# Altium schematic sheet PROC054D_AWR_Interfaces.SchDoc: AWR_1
size 558 x 431 mm; Date: Not shown in title block; ApprovedBy: Not shown in title block; CheckedBy: Not shown in title block; Author: Not shown in title block; CompanyName: Not shown in title block; DrawnBy: a0271760; Engineer: Not shown in title block; Organization: Not shown in title block; Address1: Not shown in title block; Address2: Not shown in title block; Address3: Not shown in title block; Address4: Not shown in title block; DocumentNumber: 10; Revision: Use project pAWRameter SCH_Rev; SheetNumber: 10; SheetTotal: 19; PageSetup: Record=PageOptions¦CenterHorizontal=True¦CenterVertical=True¦PrintScale=1.00¦XCorrection=1.00¦YCorrection=1.00¦PrintKind=0¦BorderSize=5000000¦LeftOffset=0¦BottomOffset=0¦Orientation=2¦PaperLength=1000¦PaperWidth=1000¦Scale=100¦PaperSource=15¦PrintQuality=600¦MediaType=1¦DitherType=10¦PaperKind=Letter¦PrintScaleMode=1
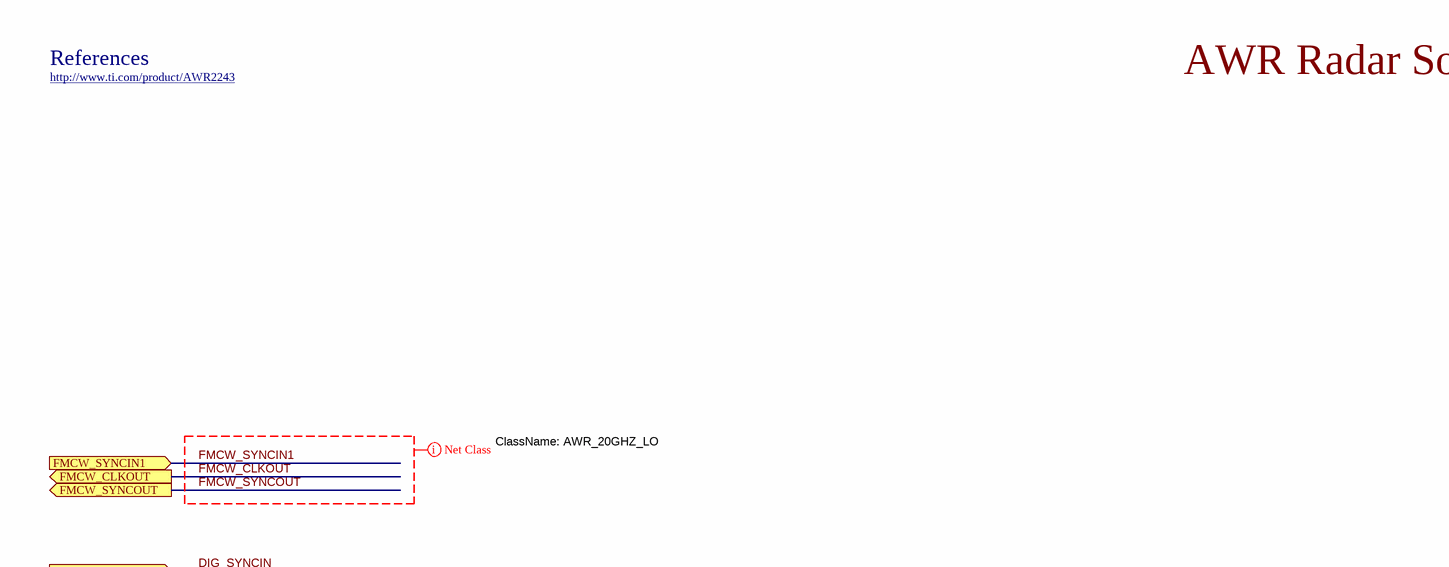
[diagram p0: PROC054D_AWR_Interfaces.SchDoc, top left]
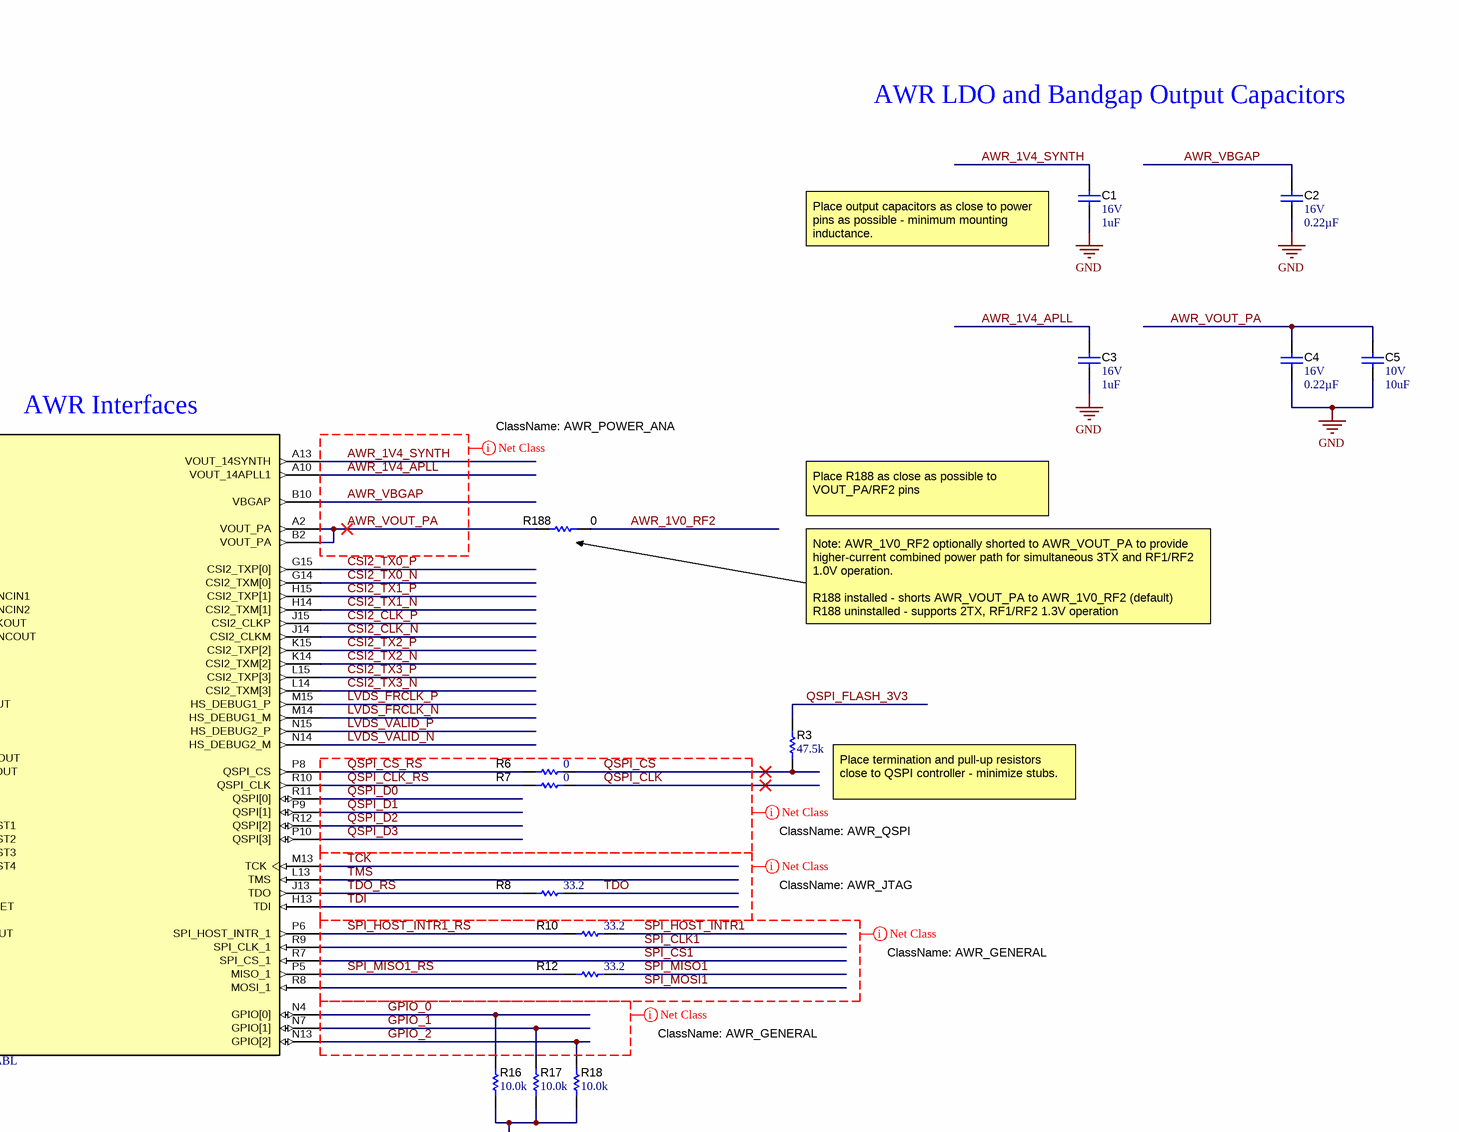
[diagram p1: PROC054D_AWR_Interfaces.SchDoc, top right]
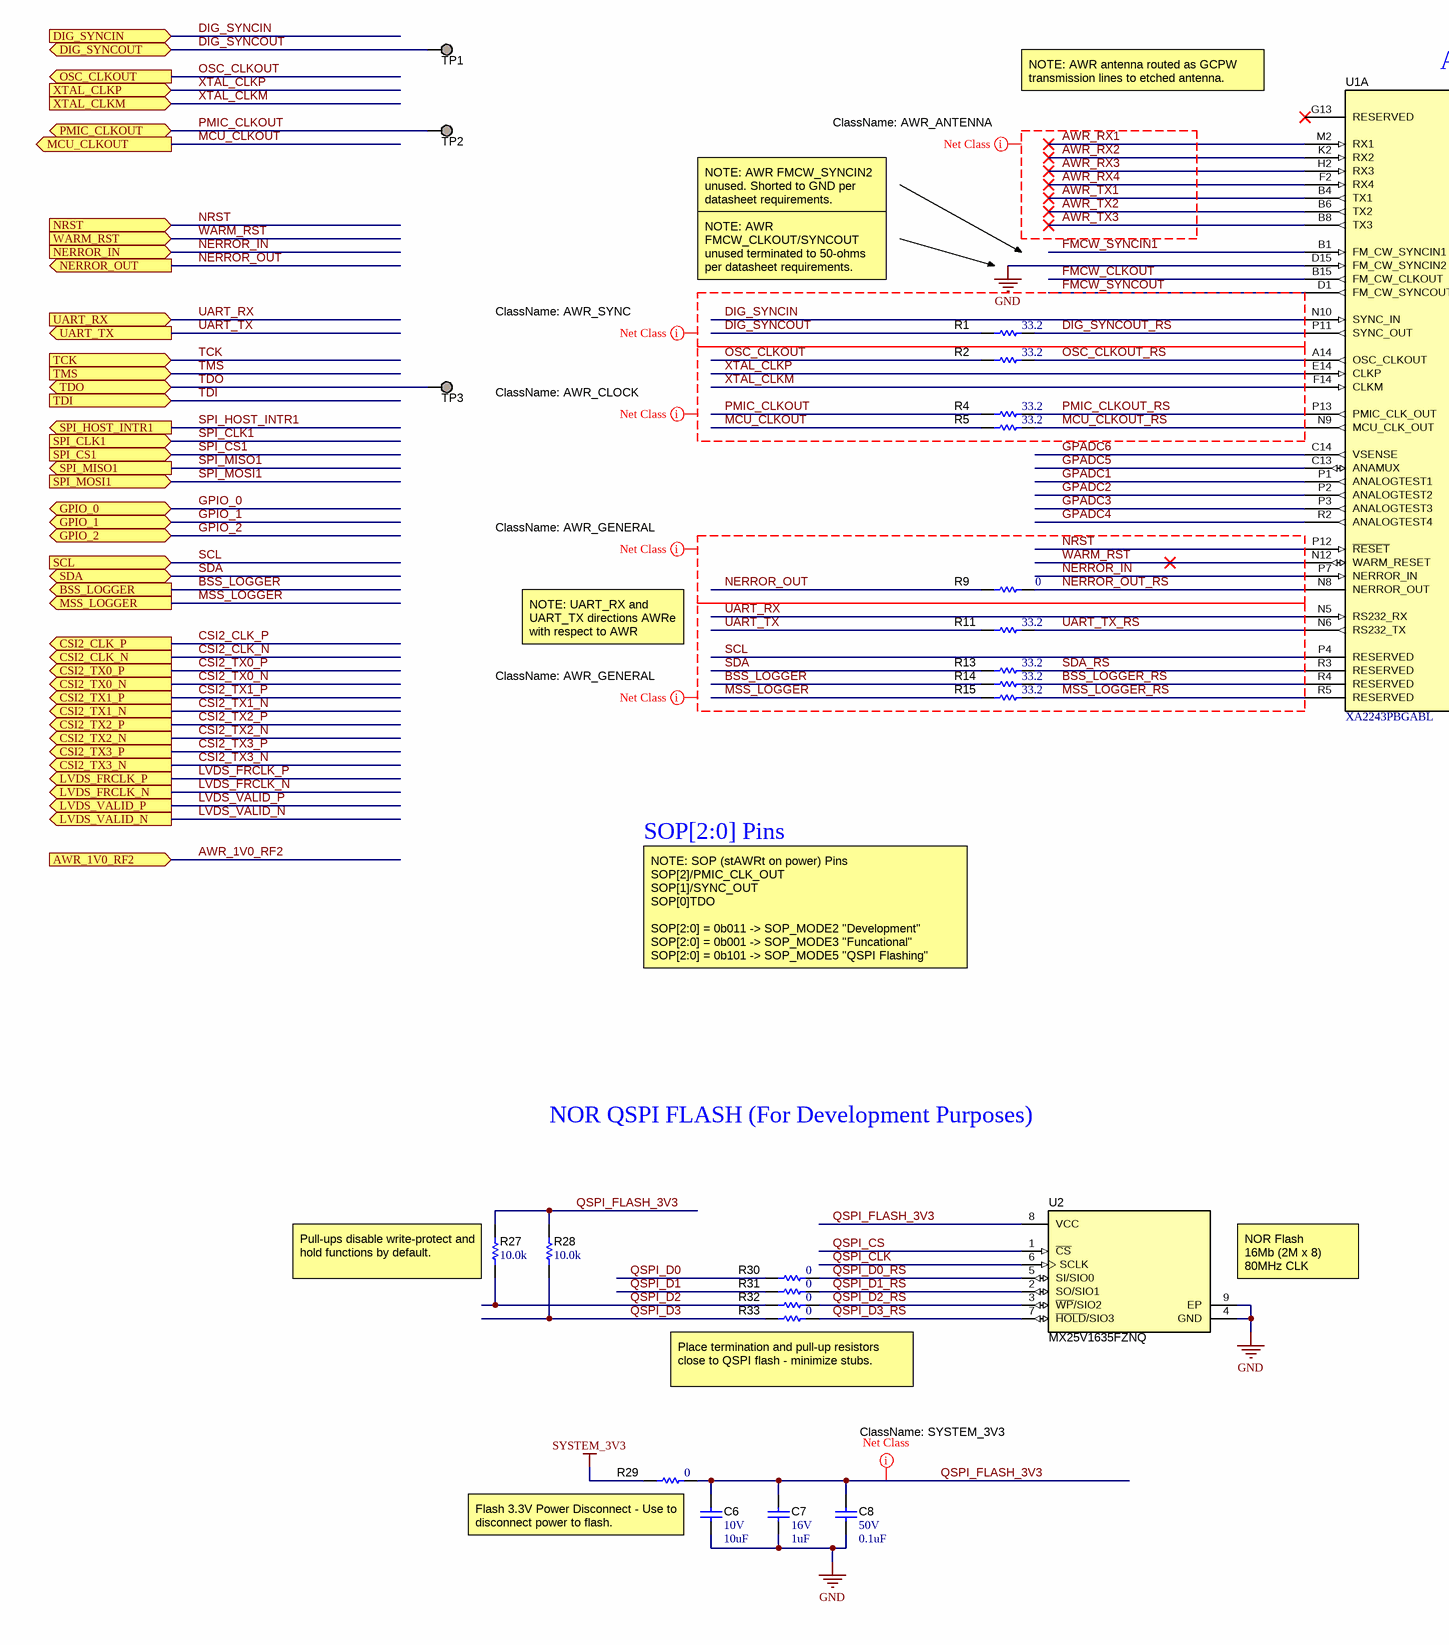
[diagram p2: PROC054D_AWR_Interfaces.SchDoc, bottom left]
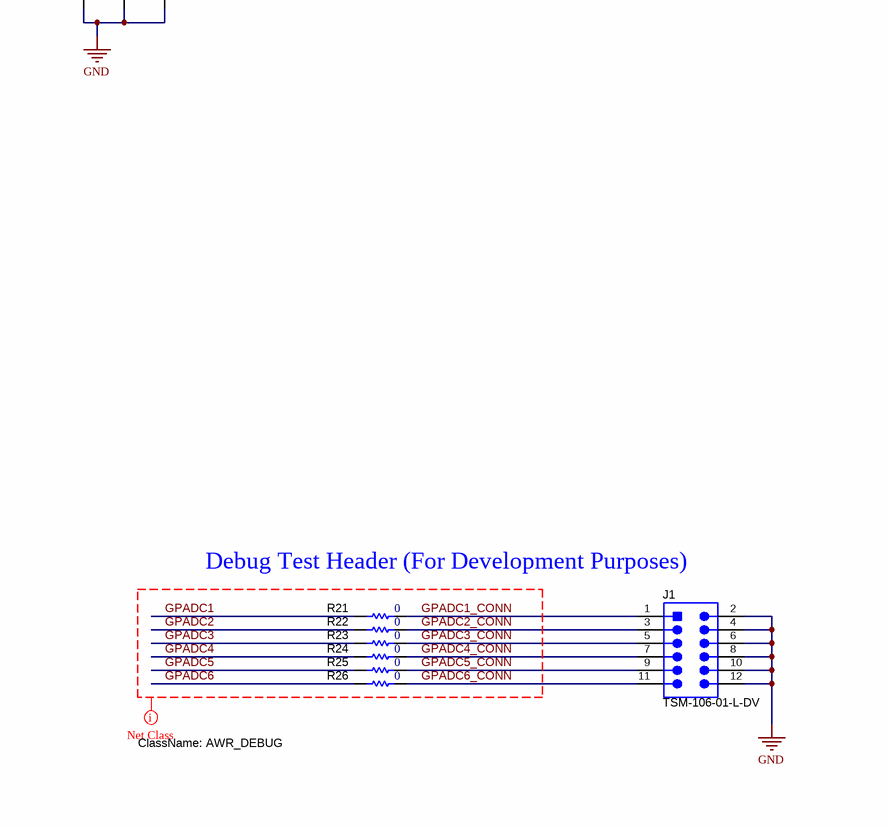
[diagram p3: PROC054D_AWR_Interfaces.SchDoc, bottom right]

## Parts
C1  VDC_V: 16V  ValueDisplayed: 1uF  [0603S]  (hidden comment: GCM188R71C105KA64D)
C2  VDC_V: 16V  ValueDisplayed: 0.22µF  [0402S]  (hidden comment: GCM155R71C224KE02D)
C3  VDC_V: 16V  ValueDisplayed: 1uF  [0603S]  (hidden comment: GCM188R71C105KA64D)
C4  VDC_V: 16V  ValueDisplayed: 0.22µF  [0402]  (hidden comment: GCM155R71C224KE02D)
C5  VDC_V: 10V  ValueDisplayed: 10uF  [0805]  (hidden comment: GCM21BR71A106KE22L)
C6  VDC_V: 10V  ValueDisplayed: 10uF  [0805L]  (hidden comment: GCM21BR71A106KE22L)
C7  VDC_V: 16V  ValueDisplayed: 1uF  [0603S]  (hidden comment: GCM188R71C105KA64D)
C8  VDC_V: 50V  ValueDisplayed: 0.1uF  [0402S]  (hidden comment: CGA2B3X7R1H104K050BB)
J1  TSM-106-01-L-DV  [Samtec_TSM-106-01-x-DV]
R1  ValueDisplayed: 33.2  [0402S]  (hidden comment: CRCW040233R2FKED)
R2  ValueDisplayed: 33.2  [0402S]  (hidden comment: CRCW040233R2FKED)
R3  ValueDisplayed: 47.5k  [0402]  (hidden comment: CRCW040247K5FKED)
R4  ValueDisplayed: 33.2  [0402S]  (hidden comment: CRCW040233R2FKED)
R5  ValueDisplayed: 33.2  [0402S]  (hidden comment: CRCW040233R2FKED)
R6  ValueDisplayed: 0  [0201]  (hidden comment: CRCW02010000Z0ED)
R7  ValueDisplayed: 0  [0201]  (hidden comment: CRCW02010000Z0ED)
R8  ValueDisplayed: 33.2  [0402S]  (hidden comment: CRCW040233R2FKED)
R9  ValueDisplayed: 0  [0402S]  (hidden comment: ERJ-2GE0R00X)
R10  ValueDisplayed: 33.2  [0402S]  (hidden comment: CRCW040233R2FKED)
R11  ValueDisplayed: 33.2  [0402S]  (hidden comment: CRCW040233R2FKED)
R12  ValueDisplayed: 33.2  [0402S]  (hidden comment: CRCW040233R2FKED)
R13  ValueDisplayed: 33.2  [0402S]  (hidden comment: CRCW040233R2FKED)
R14  ValueDisplayed: 33.2  [0402S]  (hidden comment: CRCW040233R2FKED)
R15  ValueDisplayed: 33.2  [0402S]  (hidden comment: CRCW040233R2FKED)
R16  ValueDisplayed: 10.0k  [0402]  (hidden comment: CRCW040210K0FKED)
R17  ValueDisplayed: 10.0k  [0402]  (hidden comment: CRCW040210K0FKED)
R18  ValueDisplayed: 10.0k  [0402]  (hidden comment: CRCW040210K0FKED)
R21  ValueDisplayed: 0  [0402]  (hidden comment: CRCW04020000Z0ED)
R22  ValueDisplayed: 0  [0402]  (hidden comment: CRCW04020000Z0ED)
R23  ValueDisplayed: 0  [0402]  (hidden comment: CRCW04020000Z0ED)
R24  ValueDisplayed: 0  [0402]  (hidden comment: CRCW04020000Z0ED)
R25  ValueDisplayed: 0  [0402]  (hidden comment: CRCW04020000Z0ED)
R26  ValueDisplayed: 0  [0402]  (hidden comment: CRCW04020000Z0ED)
R27  ValueDisplayed: 10.0k  [0402S]  (hidden comment: CRCW040210K0FKED)
R28  ValueDisplayed: 10.0k  [0402S]  (hidden comment: CRCW040210K0FKED)
R29  ValueDisplayed: 0  [0805_HV]  (hidden comment: CRCW08050000Z0EAHP)
R30  ValueDisplayed: 0  [0201]  (hidden comment: CRCW02010000Z0ED)
R31  ValueDisplayed: 0  [0201]  (hidden comment: CRCW02010000Z0ED)
R32  ValueDisplayed: 0  [0201]  (hidden comment: CRCW02010000Z0ED)
R33  ValueDisplayed: 0  [0201]  (hidden comment: CRCW02010000Z0ED)
R188  ValueDisplayed: 0  [0805L]  (hidden comment: PMR10EZPJ000)
TP1  TP_SM_1MM  [TP_SM_1MM]  (value not drawn)  (no BOM)
TP2  TP_SM_1MM  [TP_SM_1MM]  (value not drawn)  (no BOM)
TP3  TP_SM_1MM  [TP_SM_1MM]  (value not drawn)  (no BOM)
U1  XA2243PBGABL  [ABL0161A]  (part A of 2)
U2  MX25V1635FZNQ  [WSON-8L_6x5MM_EP]

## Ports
AWR_1V0_RF2 (in), BSS_LOGGER (out), CSI2_CLK_N (out), CSI2_CLK_P (out), CSI2_TX0_N (out), CSI2_TX0_P (out), CSI2_TX1_N (out), CSI2_TX1_P (out), CSI2_TX2_N (out), CSI2_TX2_P (out), CSI2_TX3_N (out), CSI2_TX3_P (out), DIG_SYNCIN (in), DIG_SYNCOUT (bidir), FMCW_CLKOUT (out), FMCW_SYNCIN1 (in), FMCW_SYNCOUT (out), GPIO_0 (bidir), GPIO_1 (bidir), GPIO_2 (bidir), LVDS_FRCLK_N (out), LVDS_FRCLK_P (out), LVDS_VALID_N (out), LVDS_VALID_P (out), MCU_CLKOUT (out), MSS_LOGGER (out), NERROR_IN (in), NERROR_OUT (out), NRST (in), OSC_CLKOUT (out), PMIC_CLKOUT (bidir), SCL (in), SDA (bidir), SPI_CLK1 (in), SPI_CS1 (in), SPI_HOST_INTR1 (out), SPI_MISO1 (out), SPI_MOSI1 (in), TCK (in), TDI (in), TDO (bidir), TMS (in), UART_RX (in), UART_TX (out), WARM_RST (in), XTAL_CLKM (in), XTAL_CLKP (in)

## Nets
GND: C1.2 C2.2 C3.2 C4.2 C5.2 C6.2 C7.2 C8.2 J1.2 J1.4 J1.6 J1.8 J1.10 J1.12 R16.1 R17.1 R18.1 U1.D15(FM_CW_SYNCIN2) U2.4(GND) U2.9(EP)
SYSTEM_3V3: R29.2
AWR_1V0_RF2: R188.2 ; port AWR_1V0_RF2
AWR_1V4_APLL: C3.1 U1.A10(VOUT_14APLL1)
AWR_1V4_SYNTH: C1.1 U1.A13(VOUT_14SYNTH)
AWR_RX1: U1.M2(RX1)
AWR_RX2: U1.K2(RX2)
AWR_RX3: U1.H2(RX3)
AWR_RX4: U1.F2(RX4)
AWR_TX1: U1.B4(TX1)
AWR_TX2: U1.B6(TX2)
AWR_TX3: U1.B8(TX3)
AWR_VBGAP: C2.1 U1.B10(VBGAP)
AWR_VOUT_PA: C4.1 C5.1 R188.1 U1.A2(VOUT_PA) U1.B2(VOUT_PA)
BSS_LOGGER: R14.1 ; port BSS_LOGGER
BSS_LOGGER_RS: R14.2 U1.R4(RESERVED)
CSI2_CLK_N: U1.J14(CSI2_CLKM) ; port CSI2_CLK_N
CSI2_CLK_P: U1.J15(CSI2_CLKP) ; port CSI2_CLK_P
CSI2_TX0_N: U1.G14(CSI2_TXM[0]) ; port CSI2_TX0_N
CSI2_TX0_P: U1.G15(CSI2_TXP[0]) ; port CSI2_TX0_P
CSI2_TX1_N: U1.H14(CSI2_TXM[1]) ; port CSI2_TX1_N
CSI2_TX1_P: U1.H15(CSI2_TXP[1]) ; port CSI2_TX1_P
CSI2_TX2_N: U1.K14(CSI2_TXM[2]) ; port CSI2_TX2_N
CSI2_TX2_P: U1.K15(CSI2_TXP[2]) ; port CSI2_TX2_P
CSI2_TX3_N: U1.L14(CSI2_TXM[3]) ; port CSI2_TX3_N
CSI2_TX3_P: U1.L15(CSI2_TXP[3]) ; port CSI2_TX3_P
DIG_SYNCIN: U1.N10(SYNC_IN) ; port DIG_SYNCIN
DIG_SYNCOUT: R1.1 TP1.1 ; port DIG_SYNCOUT
DIG_SYNCOUT_RS: R1.2 U1.P11(SYNC_OUT)
FMCW_CLKOUT: U1.B15(FM_CW_CLKOUT) ; port FMCW_CLKOUT
FMCW_SYNCIN1: U1.B1(FM_CW_SYNCIN1) ; port FMCW_SYNCIN1
FMCW_SYNCOUT: U1.D1(FM_CW_SYNCOUT) ; port FMCW_SYNCOUT
GPADC1: R21.1 U1.P1(ANALOGTEST1)
GPADC1_CONN: J1.1 R21.2
GPADC2: R22.1 U1.P2(ANALOGTEST2)
GPADC2_CONN: J1.3 R22.2
GPADC3: R23.1 U1.P3(ANALOGTEST3)
GPADC3_CONN: J1.5 R23.2
GPADC4: R24.1 U1.R2(ANALOGTEST4)
GPADC4_CONN: J1.7 R24.2
GPADC5: R25.1 U1.C13(ANAMUX)
GPADC5_CONN: J1.9 R25.2
GPADC6: R26.1 U1.C14(VSENSE)
GPADC6_CONN: J1.11 R26.2
GPIO_0: R16.2 U1.N4(GPIO[0]) ; port GPIO_0
GPIO_1: R17.2 U1.N7(GPIO[1]) ; port GPIO_1
GPIO_2: R18.2 U1.N13(GPIO[2]) ; port GPIO_2
LVDS_FRCLK_N: U1.M14(HS_DEBUG1_M) ; port LVDS_FRCLK_N
LVDS_FRCLK_P: U1.M15(HS_DEBUG1_P) ; port LVDS_FRCLK_P
LVDS_VALID_N: U1.N14(HS_DEBUG2_M) ; port LVDS_VALID_N
LVDS_VALID_P: U1.N15(HS_DEBUG2_P) ; port LVDS_VALID_P
MCU_CLKOUT: R5.1 ; port MCU_CLKOUT
MCU_CLKOUT_RS: R5.2 U1.N9(MCU_CLK_OUT)
MSS_LOGGER: R15.1 ; port MSS_LOGGER
MSS_LOGGER_RS: R15.2 U1.R5(RESERVED)
NERROR_IN: U1.P7(NERROR_IN) ; port NERROR_IN
NERROR_OUT: R9.1 ; port NERROR_OUT
NERROR_OUT_RS: R9.2 U1.N8(NERROR_OUT)
NRST: U1.P12(~{RESET}) ; port NRST
OSC_CLKOUT: R2.1 ; port OSC_CLKOUT
OSC_CLKOUT_RS: R2.2 U1.A14(OSC_CLKOUT)
PMIC_CLKOUT: R4.1 TP2.1 ; port PMIC_CLKOUT
PMIC_CLKOUT_RS: R4.2 U1.P13(PMIC_CLK_OUT)
QSPI_CLK: R7.2 U2.6(SCLK)
QSPI_CLK_RS: R7.1 U1.R10(QSPI_CLK)
QSPI_CS: R3.1 R6.2 U2.1(~{CS})
QSPI_CS_RS: R6.1 U1.P8(QSPI_CS)
QSPI_D0: R30.1 U1.R11(QSPI[0])
QSPI_D0_RS: R30.2 U2.5(SI/SIO0)
QSPI_D1: R31.1 U1.P9(QSPI[1])
QSPI_D1_RS: R31.2 U2.2(SO/SIO1)
QSPI_D2: R27.2 R32.1 U1.R12(QSPI[2])
QSPI_D2_RS: R32.2 U2.3(~{WP}/SIO2)
QSPI_D3: R28.2 R33.1 U1.P10(QSPI[3])
QSPI_D3_RS: R33.2 U2.7(~{HOLD}/SIO3)
QSPI_FLASH_3V3: C6.1 C7.1 C8.1 R3.2 R27.1 R28.1 R29.1 U2.8(VCC)
SCL: U1.P4(RESERVED) ; port SCL
SDA: R13.1 ; port SDA
SDA_RS: R13.2 U1.R3(RESERVED)
SPI_CLK1: U1.R9(SPI_CLK_1) ; port SPI_CLK1
SPI_CS1: U1.R7(SPI_CS_1) ; port SPI_CS1
SPI_HOST_INTR1: R10.2 ; port SPI_HOST_INTR1
SPI_HOST_INTR1_RS: R10.1 U1.P6(SPI_HOST_INTR_1)
SPI_MISO1: R12.2 ; port SPI_MISO1
SPI_MISO1_RS: R12.1 U1.P5(MISO_1)
SPI_MOSI1: U1.R8(MOSI_1) ; port SPI_MOSI1
TCK: U1.M13(TCK) ; port TCK
TDI: U1.H13(TDI) ; port TDI
TDO: R8.2 TP3.1 ; port TDO
TDO_RS: R8.1 U1.J13(TDO)
TMS: U1.L13(TMS) ; port TMS
UART_RX: U1.N5(RS232_RX) ; port UART_RX
UART_TX: R11.1 ; port UART_TX
UART_TX_RS: R11.2 U1.N6(RS232_TX)
WARM_RST: U1.N12(WARM_RESET) ; port WARM_RST
XTAL_CLKM: U1.F14(CLKM) ; port XTAL_CLKM
XTAL_CLKP: U1.E14(CLKP) ; port XTAL_CLKP

Not connected (* = marked no-connect by the designer): U1 G13(RESERVED)*

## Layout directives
net class AWR_DEBUG: GPADC1, GPADC1_CONN, GPADC2, GPADC2_CONN, GPADC3, GPADC3_CONN, GPADC4, GPADC4_CONN, GPADC5, GPADC5_CONN, GPADC6, GPADC6_CONN
net class AWR_QSPI: QSPI_CLK, QSPI_CLK_RS, QSPI_CS, QSPI_CS_RS, QSPI_D0, QSPI_D1, QSPI_D2, QSPI_D3
net class AWR_JTAG: TCK, TDI, TDO, TDO_RS, TMS
net class AWR_POWER_ANA: AWR_1V4_APLL, AWR_1V4_SYNTH, AWR_VBGAP, AWR_VOUT_PA
net class AWR_ANTENNA: AWR_RX1, AWR_RX2, AWR_RX3, AWR_RX4, AWR_TX1, AWR_TX2, AWR_TX3
net class SYSTEM_3V3: QSPI_FLASH_3V3
net class AWR_20GHZ_LO: FMCW_CLKOUT, FMCW_SYNCIN1, FMCW_SYNCOUT
net class AWR_GENERAL: BSS_LOGGER, BSS_LOGGER_RS, GPIO_0, GPIO_1, GPIO_2, MSS_LOGGER, MSS_LOGGER_RS, NERROR_IN, NERROR_OUT, NERROR_OUT_RS, NRST, SCL, SDA, SDA_RS, SPI_CLK1, SPI_CS1, SPI_HOST_INTR1, SPI_HOST_INTR1_RS, SPI_MISO1, SPI_MISO1_RS, SPI_MOSI1, UART_RX, UART_TX, UART_TX_RS, WARM_RST
net class AWR_CLOCK: MCU_CLKOUT, MCU_CLKOUT_RS, OSC_CLKOUT, OSC_CLKOUT_RS, PMIC_CLKOUT, PMIC_CLKOUT_RS, XTAL_CLKM, XTAL_CLKP
net class AWR_SYNC: DIG_SYNCIN, DIG_SYNCOUT, DIG_SYNCOUT_RS, FMCW_SYNCOUT

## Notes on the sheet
- References
- http://www.ti.com/product/AWR2243
- AWR Radar SoC - Interfaces
- AWR LDO and Bandgap Output Capacitors
- (near C1) Place output capacitors as close to power pins as possible - minimum mounting inductance.
- NOTE: AWR antenna routed as GCPW transmission lines to etched antenna.
- (near U1) AWR Interfaces
- NOTE: AWR FMCW_SYNCIN2 unused. Shorted to GND per datasheet requirements.
- Place R188 as close as possible to VOUT_PA/RF2 pins
- NOTE: AWR FMCW_CLKOUT/SYNCOUT unused terminated to 50-ohms per datasheet requirements.
- Note: AWR_1V0_RF2 optionally shorted to AWR_VOUT_PA to provide higher-current combined power path for simultaneous 3TX and RF1/RF2 1.0V operation.
  R188 installed - shorts AWR_VOUT_PA to AWR_1V0_RF2 (default)
  R188 uninstalled - supports 2TX, RF1/RF2 1.3V operation
- (near R3) Place termination and pull-up resistors close to QSPI controller - minimize stubs.
- NOTE: UART_RX and UART_TX directions AWRe with respect to AWR
- SOP[2:0] Pins
- NOTE: SOP (stAWRt on power) Pins SOP[2]/PMIC_CLK_OUT
  SOP[1]/SYNC_OUT
  SOP[0]TDO
  SOP[2:0] = 0b011 -> SOP_MODE2 "Development"
  SOP[2:0]	= 0b001 -> SOP_MODE3 "Funcational"
  SOP[2:0]	= 0b101 -> SOP_MODE5 "QSPI Flashing"
- NOR QSPI FLASH (For Development Purposes)
- (near R27) Pull-ups disable write-protect and hold functions by default.
- (near U2) NOR Flash
  16Mb (2M x 8)
  80MHz CLK
- Debug Test Header (For Development Purposes)
- (near R33) Place termination and pull-up resistors close to QSPI flash - minimize stubs.
- (near R29) Flash 3.3V Power Disconnect - Use to disconnect power to flash.

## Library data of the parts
C1 C7 = CMP-0007136-5: CAP, CERM, 1 uF, 16 V, +/- 10%, X7R, AEC-Q200 Grade 1, 0603; Manufacturer: MuRata; TaMin_C: -55°C; Polarized: N; SizeAreaWB_mm2: 4.68; Value1: Unknown; U/M: EA; Value: 1uF; TaMax_C: 125°C; SizeZ_mm: 1; SizeX_mm: 1.6; SizeY_mm: 0.8; Cap_Case: 0603; SizeArea_mm2: 1.28; CompType: Capacitor; AEC Qualified: Y; Cap_F: 1µF; AEC Category: Q200
C2 = CMP-0078265-1: CAP, CERM, 0.22 µF, 16 V,+/- 10%, X7R, AEC-Q200 Grade 1, 0402; Manufacturer: MuRata; TaMin_C: -55°C; Polarized: N; SizeAreaWB_mm2: 3; U/M: EA; Value: 0.22uF; TaMax_C: 125°C; SizeZ_mm: 0.6; SizeX_mm: 1; SizeY_mm: 0.5; Cap_Case: 0402; CompType: Capacitor; AEC Qualified: Y; Cap_F: 220nF; AEC Category: Q200
C3 = CMP-0007136-5: CAP, CERM, 1 uF, 16 V, +/- 10%, X7R, AEC-Q200 Grade 1, 0603; Manufacturer: MuRata; TaMin_C: -55°C; Polarized: N; SizeAreaWB_mm2: 4.68; Value1: Unknown; U/M: EA; Value: 1uF; TaMax_C: 125°C; SizeZ_mm: 1; SizeX_mm: 1.6; SizeY_mm: 0.8; Cap_Case: 0603; SizeArea_mm2: 1.28; AEC Qualified: Y; Cap_F: 1µF; AEC Category: Q200
C4 = CMP-0078265-1: CAP, CERM, 0.22 µF, 16 V,+/- 10%, X7R, AEC-Q200 Grade 1, 0402; Manufacturer: MuRata; TaMin_C: -55°C; Polarized: N; SizeAreaWB_mm2: 3; U/M: EA; Value: 0.22uF; TaMax_C: 125°C; SizeZ_mm: 0.6; SizeX_mm: 1; SizeY_mm: 0.5; CompType: Capacitor; AEC Qualified: Y; Cap_F: 220nF; AEC Category: Q200
C5 = CMP-0008017-2: CAP, CERM, 10 uF, 10 V, +/- 10%, X7R, 0805; Manufacturer: MuRata; TaMin_C: -55°C; Polarized: N; SizeAreaWB_mm2: 6.75; Value1: Unknown; U/M: EA; Value: 10uF; TaMax_C: 125°C; SizeZ_mm: 1.45; SizeX_mm: 2; SizeY_mm: 1.25; SizeArea_mm2: 2.5; Cap_F: 10µF; AEC Category: Q200
C6 = CMP-0008017-2: CAP, CERM, 10 uF, 10 V, +/- 10%, X7R, 0805; Manufacturer: MuRata; TaMin_C: -55°C; Polarized: N; SizeAreaWB_mm2: 6.75; Value1: Unknown; U/M: EA; Value: 10uF; TaMax_C: 125°C; SizeZ_mm: 1.45; SizeX_mm: 2; SizeY_mm: 1.25; Cap_Case: 0805; SizeArea_mm2: 2.5; CompType: Capacitor; Cap_F: 10µF; AEC Category: Q200
C8 = CMP-0006325-2: CAP, CERM, 0.1 uF, 50 V, +/- 10%, X7R, AEC-Q200 Grade 1, 0402; Manufacturer: TDK; TaMin_C: -55°C; ESR_ohm: 0.039064; Polarized: N; SizeAreaWB_mm2: 3; Value1: 0.039064 ohm; U/M: EA; Value: 0.1uF; TaMax_C: 125°C; SizeZ_mm: 0.6; SizeX_mm: 1; SizeY_mm: 0.5; Cap_Case: 0402; AEC Qualified: Y; Cap_F: 100nF; IRMS_A: 8.14669dA; AEC Category: Q200
J1 = CMP-0075594-2: Header, 2.54mm, 6x2, Gold, SMT; Manufacturer: Samtec; Pitch_mm: 2.54; Gender: Male; Cert_CSA: Y; Green_REACh: Passed; Current_A: 4.9A; Voltage_V: 475V; Shrouded: N; Green_Lifecycle: Active; Row_Count: 2
R1 R2 R4 R5 R8 R10-R13 = CMP-0026299-2: RES, 33.2, 1%, 0.063 W, AEC-Q200 Grade 0, 0402; Manufacturer: Vishay-Dale; Power_W: 63mW; TempCo: 100 ppm/C; Value_Code: 33R2; Value: 33.2; EIA_Code: E96; SizeX_mm: 1; SizeY_mm: 0.5; SizeZ_mm: 0.6; Value2: 0.063W; CompType: Resistor; AEC Qualified: Y; VDC_V: 50V; AEC Category: Q200; AEC Grade: 0
R3 = CMP-0026395-2: RES, 47.5 k, 1%, 0.063 W, AEC-Q200 Grade 0, 0402; Manufacturer: Vishay-Dale; Power_W: 63mW; TempCo: 100 ppm/C; Value_Code: 47k5; Value: 47.5k; EIA_Code: E96; SizeX_mm: 1; SizeY_mm: 0.5; SizeZ_mm: 0.6; Value2: 0.063W; AEC Qualified: Y; VDC_V: 50V; AEC Category: Q200; AEC Grade: 0
R6 R7 R30-R33 = CMP-0027008-4: RES, 0, 5%, 0.05 W, 0201; Manufacturer: Vishay-Dale; Power_W: 50mW; TempCo: ppm/C; Value_Code: 0000; Value: 0; EIA_Code: E24; SizeX_mm: 0.6; SizeY_mm: 0.3; SizeZ_mm: 0.26; Value2: 0.05W; SizeArea_mm2: 0.18; CompType: Resistor; AEC Qualified: N; AEC Category: Q200
R9 = CMP-0026992-3: RES, 0, 5%, 0.1 W, AEC-Q200 Grade 0, 0402; Manufacturer: Panasonic; Power_W: 100mW; TempCo: 600 ppm/C; Value_Code: 0000; Value: 0; EIA_Code: E24; SizeX_mm: 1; SizeY_mm: 0.5; SizeZ_mm: 0.6; Value2: 0.1W; CompType: Resistor; AEC Qualified: Y; VDC_V: 50V; AEC Category: Q200; SizeAreaWB_mm2: 3
R14 R15 = CMP-0026299-2: RES, 33.2, 1%, 0.063 W, AEC-Q200 Grade 0, 0402; Manufacturer: Vishay-Dale; Power_W: 63mW; TempCo: 100 ppm/C; Value_Code: 33R2; Value: 33.2; EIA_Code: E96; SizeX_mm: 1; SizeY_mm: 0.5; SizeZ_mm: 0.6; Value2: 0.063W; AEC Qualified: Y; VDC_V: 50V; AEC Category: Q200; AEC Grade: 0
R16 R27 R28 = CMP-0025958-3: RES, 10.0 k, 1%, 0.063 W, AEC-Q200 Grade 0, 0402; Manufacturer: Vishay-Dale; Power_W: 63mW; TempCo: 100 ppm/C; Value_Code: 10k0; Value: 10.0k; EIA_Code: E96; Res_ohm: 10k; SizeX_mm: 1; SizeY_mm: 0.5; SizeZ_mm: 0.6; Value2: 0.063W; CompType: Resistor; AEC Qualified: Y; VDC_V: 50V; AEC Category: Q200; AEC Grade: 0
R17 R18 = CMP-0025958-3: RES, 10.0 k, 1%, 0.063 W, AEC-Q200 Grade 0, 0402; Manufacturer: Vishay-Dale; Power_W: 63mW; TempCo: 100 ppm/C; Value_Code: 10k0; Value: 10.0k; EIA_Code: E96; Res_ohm: 10k; SizeX_mm: 1; SizeY_mm: 0.5; SizeZ_mm: 0.6; Value2: 0.063W; AEC Qualified: Y; VDC_V: 50V; AEC Category: Q200; AEC Grade: 0
R21-R26 = CMP-0026822-3: RES, 0, 5%, 0.063 W, AEC-Q200 Grade 0, 0402; Manufacturer: Vishay-Dale; Power_W: 63mW; TempCo: 200 ppm/C; Value_Code: 0000; Value: 0; EIA_Code: E24; SizeX_mm: 1; SizeY_mm: 0.5; SizeZ_mm: 0.6; Value2: 0.063W; CompType: Resistor; AEC Qualified: Y; VDC_V: 50V; AEC Category: Q200
R29 = CMP-0020443-3: RES, 0, 5%, 0.333 W, AEC-Q200 Grade 0, 0805; Manufacturer: Vishay-Dale; Power_W: 333mW; TempCo: 200 ppm/C; Value_Code: 0000; Value: 0; EIA_Code: E24; SizeX_mm: 2; SizeY_mm: 1.25; SizeZ_mm: 1.45; Value2: 0.333W; SizeArea_mm2: 2.5; AEC Qualified: Y; AEC Category: Q200; VDC_V: 150V
R188 = CMP-0081857-1: RES, 0, 0%,  W, AEC-Q200 Grade 0, 0805; Manufacturer: Rohm; SizeAreaWB_mm2: 6.75; SizeArea_mm2: 2.5; AEC Qualified: Y; AEC Category: Q200; Value: 0; SizeZ_mm: 1.45; SizeY_mm: 1.25; CompType: Resistor; SizeX_mm: 2
TP1-TP3 = CMP-0003825-1: 1mm Test Point, SMT; Manufacturer: Any
U1 = CMP-0082537-1: Single Chip 77 and 79 GHz FMCW Transceiver, ABL0161A (FCBGA-161); Alternate Manufacturer: Texas Instruments; SizeAreaWB_mm2: 153.76; Rating: Automotive; SizeZ_mm: 1.17; SizeX_mm: 10.4; SizeArea_mm2: 108.16; CompType: IC; AEC Qualified: Y; AEC Category: Q200
U2 = CMP-0079267-1: 2.3V-3.6V, 16M-BIT [x 1/x 2/x 4] CMOS FLASH Memory, WSON-8; Manufacturer: Macronix International Co., LTD; SizeArea_mm2: 30; SizeAreaWB_mm2: 56; SizeY_mm: 5; SizeZ_mm: 0.8; SizeX_mm: 6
